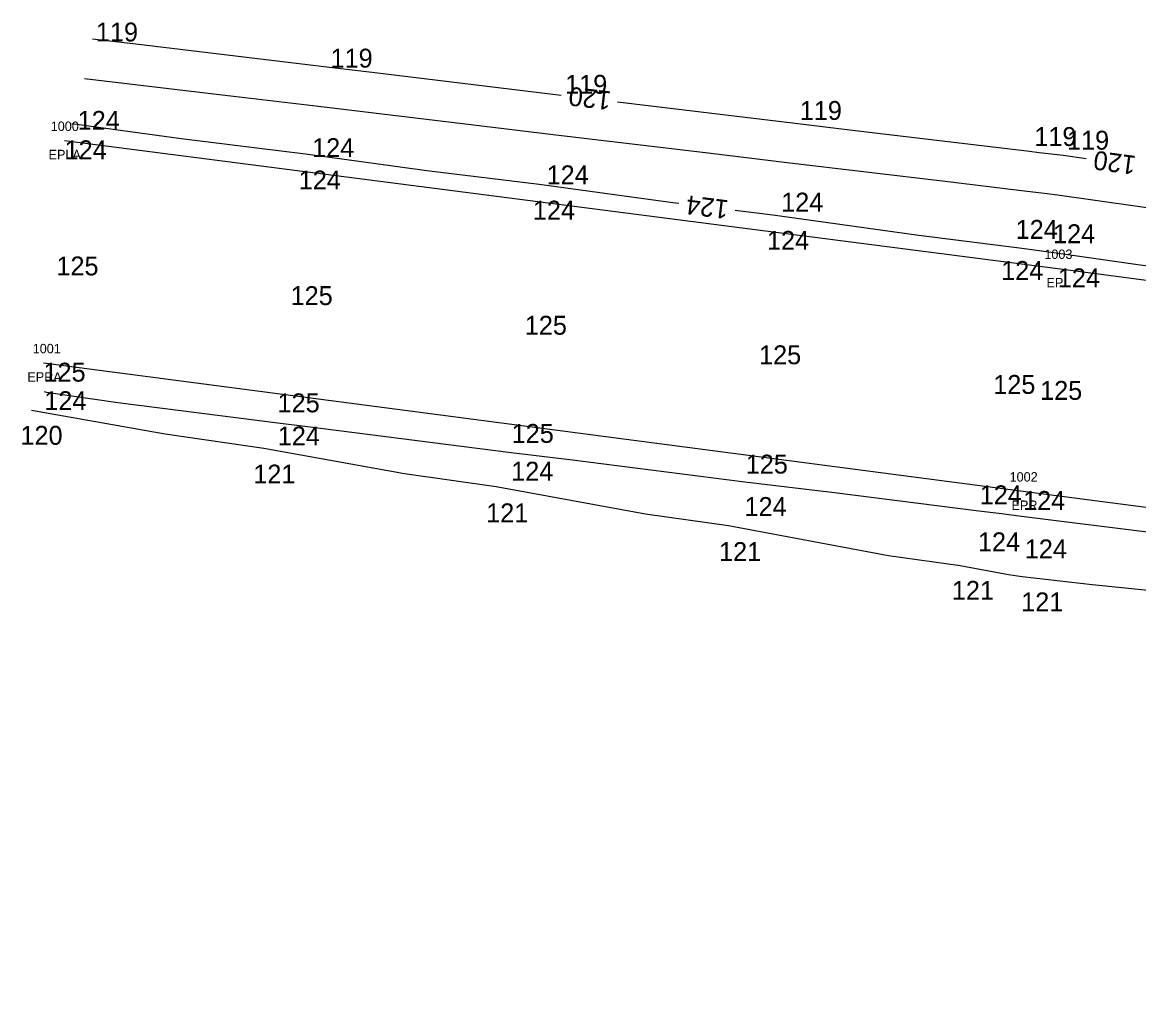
# Model space of a CAD drawing. Extents: x 2080741 to 2082054, y 730754 to 730981.
# Drawn here: x 2080937.6 to 2081055.9, y 730855.5 to 730959.9 of the extents above; entities that cross this region are included whole.
import ezdxf

# ---------------------------------------------------------------- set-up
doc = ezdxf.new("R2010")
doc.units = 0
for name, color, linetype in [('Default', 7, 'Continuous'), ('RD_DTM_Major1', 7, 'Continuous'), ('RD_DTM_Major1_Lbl', 7, 'Continuous'), ('RD_DTM_Minor1', 7, 'Continuous'), ('RD_DTM_Minor2_Lbl', 7, 'Continuous'), ('RD_EX_Road', 7, 'Continuous'), ('RD_EX_Road_txCode', 7, 'Continuous'), ('RD_SMD_Locator', 7, 'Continuous')]:
    doc.layers.add(name, color=color, linetype=linetype)

msp = doc.modelspace()

# ---------------------------------------------------------------- linework, layer by layer
at = {"layer": 'RD_DTM_Major1'}
for points in [[(2080945.08, 730958.14), (2080949.65, 730957.6), (2080969.88, 730955.16), (2080974.96, 730954.56), (2080994.69, 730952.18), (2080994.72, 730952.18)], [(2081000.68, 730951.47), (2081019.49, 730949.2), (2081025.54, 730948.48), (2081044.3, 730946.23), (2081045.33, 730946.1), (2081047.88, 730945.8), (2081050.31, 730945.45)]]:
    msp.add_lwpolyline(points, dxfattribs=at)
at = {"layer": 'RD_DTM_Minor1'}
for points in [[(2080944.21, 730953.95), (2080959.99, 730952.07), (2080969.02, 730950.99), (2080985.13, 730949.07), (2080993.84, 730948.02), (2081010.26, 730946.06), (2081018.65, 730945.05), (2081035.38, 730943.06), (2081043.46, 730942.09), (2081046.16, 730941.77), (2081047.26, 730941.63), (2081064.21, 730939.21), (2081072.02, 730938.31), (2081089.65, 730935.79), (2081096.78, 730934.95), (2081114.99, 730932.34), (2081121.53, 730931.56), (2081140.26, 730928.88), (2081142.59, 730928.6)], [(2081007.16, 730940.68), (2081006.52, 730940.76), (2080992.38, 730942.71), (2080980.47, 730944.17), (2080967.63, 730945.93), (2080954.45, 730947.54), (2080942.89, 730949.12)], [(2081211.07, 730911.65), (2081202.38, 730913.52), (2081198.92, 730914.04), (2081198.72, 730914.07), (2081175.84, 730917.52), (2081173.95, 730917.76), (2081153.55, 730920.81), (2081149.15, 730921.34), (2081147.17, 730921.6), (2081146.27, 730921.73), (2081128.37, 730924.15), (2081121.48, 730925.14), (2081104.08, 730927.49), (2081096.7, 730928.57), (2081079.79, 730930.85), (2081071.91, 730932), (2081055.51, 730934.22), (2081047.12, 730935.44), (2081043.24, 730935.98), (2081041.84, 730936.15), (2081032.59, 730937.3), (2081017.11, 730939.45), (2081013.12, 730939.94)], [(2080939.94, 730920.78), (2080940.19, 730920.73), (2080947.77, 730919.63), (2080964.69, 730917.45), (2080967.57, 730917.1), (2080989.42, 730914.32), (2080995.89, 730913.53), (2081014.17, 730911.22), (2081023.65, 730910.07), (2081038.93, 730908.15), (2081041.06, 730907.89), (2081043.72, 730907.56), (2081055.92, 730906.04), (2081068.53, 730904.59), (2081080.87, 730903.05), (2081093.35, 730901.61), (2081105.83, 730900.06), (2081118.17, 730898.64), (2081130.8, 730897.06), (2081138.42, 730896.18)], [(2080938.6, 730918.82), (2080952.78, 730916.31), (2080963.22, 730914.79), (2080978.13, 730912.11), (2080987.83, 730910.72), (2081003.64, 730907.83), (2081012.41, 730906.58), (2081029.38, 730903.43), (2081036.96, 730902.37), (2081042.06, 730901.4), (2081043.54, 730901.19), (2081050.94, 730900.35), (2081068.36, 730898.59), (2081078.49, 730897.44), (2081093.2, 730895.93), (2081105.27, 730894.56), (2081118.03, 730893.23), (2081131.57, 730891.7), (2081136.57, 730891.17)]]:
    msp.add_lwpolyline(points, dxfattribs=at)
at = {"layer": 'RD_EX_Road'}
for points in [[(2080942.12, 730947.38), (2081047.3, 730933.82), (2081149.12, 730920.41), (2081250.8, 730907.26), (2081354.36, 730894.35), (2081413.29, 730885.99), (2081474.17, 730877.58), (2081469.7, 730866.51)], [(2080939.88, 730923.83), (2081043.62, 730910.24), (2081146.95, 730896.77), (2081220.01, 730886.78), (2081221.02, 730889.92), (2081249.39, 730886.24), (2081293.86, 730880.24), (2081293.66, 730877.5), (2081351.01, 730869.76), (2081411.83, 730862.33), (2081465.27, 730855.52), (2081469.7, 730866.51)]]:
    msp.add_lwpolyline(points, dxfattribs=at)
at = {"layer": 'RD_SMD_Locator'}
for centre in [(2080942.12, 730947.38), (2081047.3, 730933.82), (2080939.88, 730923.83), (2081043.62, 730910.24)]:
    msp.add_circle(centre, 0.001, dxfattribs=at)

# ---------------------------------------------------------------- texts
at = {"layer": 'Default'}
for s, p in [('119', (2080945.43, 730957.86)), ('119', (2080970.28, 730955.09)), ('119', (2080995.12, 730952.32)), ('119', (2081019.97, 730949.55)), ('124', (2080943.5, 730948.5)), ('119', (2081044.81, 730946.79)), ('124', (2080968.33, 730945.61)), ('119', (2081048.27, 730946.4)), ('124', (2080942.12, 730945.38)), ('124', (2080966.91, 730942.18)), ('124', (2080993.16, 730942.73)), ('124', (2081018, 730939.84)), ('124', (2080991.71, 730938.99)), ('124', (2081042.83, 730936.95)), ('124', (2081046.79, 730936.49)), ('124', (2081016.5, 730935.79)), ('125', (2080941.25, 730933.08)), ('124', (2081041.3, 730932.6)), ('124', (2081047.3, 730931.82)), ('125', (2080966.05, 730929.94)), ('125', (2080990.85, 730926.8)), ('125', (2081015.66, 730923.67)), ('125', (2080939.88, 730921.83)), ('125', (2081040.46, 730920.53)), ('125', (2081045.42, 730919.9)), ('124', (2080939.97, 730918.81)), ('125', (2080964.67, 730918.58)), ('120', (2080937.44, 730915.14)), ('124', (2080964.69, 730915.07)), ('125', (2080989.46, 730915.34)), ('124', (2080989.41, 730911.34)), ('125', (2081014.25, 730912.09)), ('121', (2080962.1, 730911.04)), ('124', (2081039.03, 730908.84)), ('124', (2081043.62, 730908.24)), ('121', (2080986.76, 730906.93)), ('124', (2081014.12, 730907.6)), ('124', (2081038.84, 730903.86)), ('124', (2081043.8, 730903.11)), ('121', (2081011.42, 730902.83)), ('121', (2081036.08, 730898.72)), ('121', (2081043.42, 730897.5))]:
    msp.add_text(s, height=2, dxfattribs=at).set_placement(p)
at = {"layer": 'RD_DTM_Major1_Lbl'}
for rotation, p in [(173.2014, (2081000.07, 730952.55)), (172.3463, (2081055.66, 730945.71))]:
    msp.add_text('120', height=2, rotation=rotation, dxfattribs=at).set_placement(p)
at = {"layer": 'RD_DTM_Minor2_Lbl'}
msp.add_text('124', height=2, rotation=172.9482, dxfattribs=at).set_placement((2081012.51, 730941.02))
at = {"layer": 'RD_EX_Road_txCode'}
for s, p in [('1000', (2080940.65, 730948.38)), ('EPLA', (2080940.42, 730945.38)), ('1003', (2081045.87, 730934.82)), ('EPL', (2081046.1, 730931.82)), ('1001', (2080938.74, 730924.83)), ('EPRA', (2080938.17, 730921.83)), ('1002', (2081042.19, 730911.24)), ('EPR', (2081042.39, 730908.24))]:
    msp.add_text(s, height=1, dxfattribs=at).set_placement(p)

doc.saveas('drawing.dxf')
